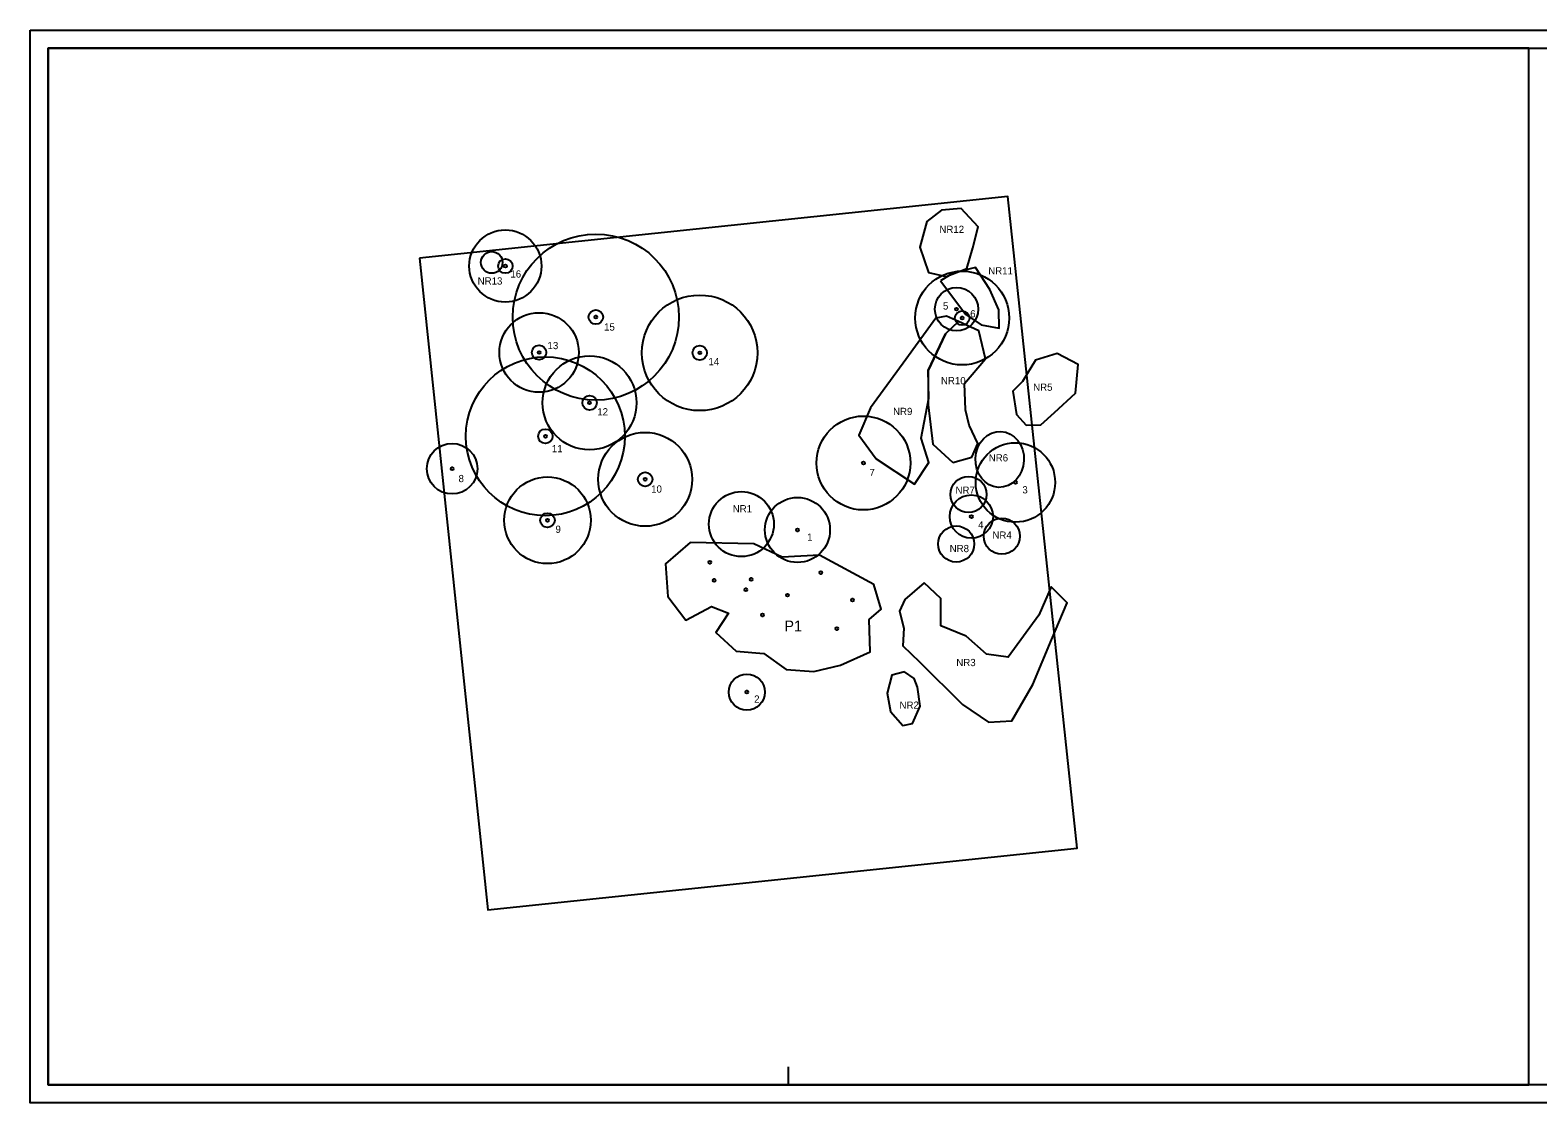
# Model space of a CAD drawing. Extents: x -539518 to -539203, y -1156262 to -1156114.
# Drawn here: x -539517.8 to -539309.1, y -1156262.1 to -1156113.6 of the extents above; entities that cross this region are included whole.
import ezdxf

# ---------------------------------------------------------------- set-up
doc = ezdxf.new("R2010")
doc.units = 0
for name, color, linetype in [('hranice řešeného území', 7, 'Continuous'), ('odstraňovaný keř', 7, 'Continuous'), ('odstraňovaný strom', 7, 'Continuous'), ('pěstební ošetření', 7, 'Continuous'), ('rámeček', 7, 'Continuous'), ('stávající keř', 7, 'Continuous'), ('stávající porost', 7, 'Continuous'), ('stávající strom', 7, 'Continuous'), ('text inventarizace', 7, 'Continuous')]:
    doc.layers.add(name, color=color, linetype=linetype)

msp = doc.modelspace()

# ---------------------------------------------------------------- linework, layer by layer
at = {"layer": 'hranice řešeného území'}
msp.add_lwpolyline([(-539463.88, -1156145.1), (-539454.44, -1156235.32), (-539372.85, -1156226.79), (-539382.42, -1156136.58)], close=True, dxfattribs=at)
at = {"layer": 'odstraňovaný keř'}
for centre, radius in [((-539453.9, -1156145.71), 1.5), ((-539387.89, -1156177.83), 2.5)]:
    msp.add_circle(centre, radius, dxfattribs=at)
msp.add_ellipse((-539383.56, -1156172.98), major_axis=(0.17, 3.87), ratio=0.867323, dxfattribs=at)
at = {"layer": 'odstraňovaný strom'}
for centre, radius in [((-539389.53, -1156152.19), 3), ((-539389.53, -1156152.19), 0.2), ((-539402.43, -1156173.48), 6.5), ((-539402.43, -1156173.48), 0.2), ((-539411.56, -1156182.75), 4.5), ((-539411.56, -1156182.75), 0.2)]:
    msp.add_circle(centre, radius, dxfattribs=at)
at = {"layer": 'pěstební ošetření'}
for centre in [(-539452.01, -1156146.21), (-539439.48, -1156153.28), (-539388.76, -1156153.41), (-539447.34, -1156158.18), (-539425.1, -1156158.23), (-539440.35, -1156165.15), (-539446.47, -1156169.78), (-539432.65, -1156175.74), (-539446.18, -1156181.41)]:
    msp.add_circle(centre, 1, dxfattribs=at)
at = {"layer": 'rámeček'}
msp.add_line((-539412.8, -1156259.56), (-539412.8, -1156257.06), dxfattribs=at)
for points in [[(-539517.8, -1156113.56), (-539202.8, -1156113.56), (-539202.8, -1156262.06), (-539517.8, -1156262.06)], [(-539310.3, -1156259.56), (-539310.3, -1156116.06), (-539515.3, -1156116.06), (-539515.3, -1156259.56)], [(-539515.3, -1156116.06), (-539205.3, -1156116.06), (-539205.3, -1156259.56), (-539515.3, -1156259.56)]]:
    msp.add_lwpolyline(points, close=True, dxfattribs=at)
at = {"layer": 'stávající keř'}
for points in [[(-539391.62, -1156138.48), (-539393.65, -1156140.04), (-539394.6, -1156143.62), (-539393.42, -1156147.13), (-539390.97, -1156147.65), (-539388.1, -1156146.54), (-539387.3, -1156143.71), (-539386.55, -1156140.78), (-539388.92, -1156138.25)], [(-539391.76, -1156148.27), (-539388.26, -1156152.91), (-539386.15, -1156154.37), (-539383.62, -1156154.82), (-539383.69, -1156152.26), (-539384.93, -1156149.45), (-539386.93, -1156146.43), (-539390.05, -1156147.2)], [(-539392.4, -1156153.42), (-539396.93, -1156159.64), (-539401.46, -1156165.86), (-539403.05, -1156169.61), (-539400.66, -1156172.91), (-539395.34, -1156176.41), (-539393.39, -1156173.43), (-539394.42, -1156170.02), (-539393.38, -1156164.51), (-539393.48, -1156160.66), (-539391.05, -1156155.62), (-539389.26, -1156153.91), (-539390.91, -1156153.15)], [(-539390.04, -1156173.4), (-539387.4, -1156172.65), (-539386.59, -1156170.8), (-539387.8, -1156168.26), (-539388.28, -1156166.1), (-539388.45, -1156162.48), (-539385.51, -1156159.07), (-539386.45, -1156155.18), (-539389.26, -1156153.91), (-539391.05, -1156155.62), (-539393.48, -1156160.66), (-539393.45, -1156165.42), (-539392.84, -1156170.86)], [(-539378.59, -1156159.24), (-539380.39, -1156162.21), (-539381.74, -1156163.53), (-539381.23, -1156166.77), (-539379.88, -1156168.23), (-539377.89, -1156168.19), (-539375.99, -1156166.47), (-539373.05, -1156163.81), (-539372.7, -1156159.86), (-539375.59, -1156158.32)], [(-539394.04, -1156190.09), (-539396.68, -1156192.36), (-539397.45, -1156193.98), (-539396.82, -1156196.34), (-539396.97, -1156198.79), (-539394.65, -1156201.01), (-539388.72, -1156206.92), (-539385.13, -1156209.36), (-539381.89, -1156209.19), (-539378.98, -1156204.15), (-539376.38, -1156197.94), (-539374.24, -1156192.83), (-539376.45, -1156190.63), (-539378.14, -1156194.56), (-539382.4, -1156200.37), (-539385.37, -1156199.96), (-539388.21, -1156197.46), (-539391.7, -1156196), (-539391.73, -1156192.22)], [(-539396.74, -1156202.39), (-539398.5, -1156202.84), (-539399.14, -1156205.34), (-539398.69, -1156207.88), (-539396.96, -1156209.8), (-539395.66, -1156209.53), (-539394.58, -1156207.13), (-539394.93, -1156204.52), (-539395.41, -1156203.32)]]:
    msp.add_lwpolyline(points, close=True, dxfattribs=at)
for centre, radius in [((-539419.33, -1156181.94), 4.5), ((-539389.58, -1156184.69), 2.5), ((-539383.26, -1156183.62), 2.5)]:
    msp.add_circle(centre, radius, dxfattribs=at)
at = {"layer": 'stávající porost'}
msp.add_lwpolyline([(-539426.42, -1156184.5), (-539429.82, -1156187.45), (-539429.53, -1156191.94), (-539427.03, -1156195.25), (-539423.45, -1156193.33), (-539421.11, -1156194.26), (-539422.86, -1156196.95), (-539420.03, -1156199.51), (-539416.23, -1156199.87), (-539413.11, -1156202.06), (-539409.31, -1156202.33), (-539405.6, -1156201.46), (-539401.48, -1156199.64), (-539401.65, -1156195.14), (-539399.99, -1156193.73), (-539400.97, -1156190.28), (-539408.51, -1156186.22), (-539413.68, -1156186.53), (-539417.6, -1156184.67)], close=True, dxfattribs=at)
at = {"layer": 'stávající strom'}
for centre, radius in [((-539452.01, -1156146.21), 5), ((-539439.48, -1156153.28), 11.5), ((-539452.01, -1156146.21), 0.2), ((-539388.76, -1156153.41), 6.5), ((-539425.1, -1156158.23), 8), ((-539447.34, -1156158.18), 5.5), ((-539439.48, -1156153.28), 0.2), ((-539388.76, -1156153.41), 0.2), ((-539446.47, -1156169.78), 11), ((-539447.34, -1156158.18), 0.2), ((-539440.35, -1156165.15), 6.5), ((-539425.1, -1156158.23), 0.2), ((-539440.35, -1156165.15), 0.2), ((-539446.47, -1156169.78), 0.2), ((-539432.65, -1156175.74), 6.5), ((-539459.38, -1156174.27), 3.5), ((-539381.39, -1156176.17), 5.5), ((-539459.38, -1156174.27), 0.2), ((-539446.18, -1156181.41), 6), ((-539432.65, -1156175.74), 0.2), ((-539381.39, -1156176.17), 0.2), ((-539387.49, -1156180.9), 3), ((-539446.18, -1156181.41), 0.2), ((-539387.49, -1156180.9), 0.2), ((-539423.7, -1156187.22), 0.2), ((-539408.31, -1156188.65), 0.2), ((-539423.08, -1156189.73), 0.2), ((-539418.71, -1156191.02), 0.2), ((-539417.98, -1156189.59), 0.2), ((-539412.93, -1156191.77), 0.2), ((-539403.95, -1156192.46), 0.2), ((-539416.41, -1156194.51), 0.2), ((-539406.12, -1156196.4), 0.2), ((-539418.58, -1156205.19), 2.5), ((-539418.58, -1156205.19), 0.2)]:
    msp.add_circle(centre, radius, dxfattribs=at)

# ---------------------------------------------------------------- texts
at = {"layer": 'text inventarizace'}
for s, p in [('NR12', (-539391.91, -1156141.63)), ('16', (-539451.31, -1156147.81)), ('NR11', (-539385.15, -1156147.37)), ('NR13', (-539455.84, -1156148.78)), ('5', (-539391.42, -1156152.24)), ('6', (-539387.65, -1156153.32)), ('15', (-539438.34, -1156155.15)), ('13', (-539446.17, -1156157.72)), ('14', (-539423.89, -1156159.94)), ('NR10', (-539391.7, -1156162.58)), ('NR5', (-539378.93, -1156163.48)), ('12', (-539439.28, -1156166.89)), ('NR9', (-539398.33, -1156166.84)), ('11', (-539445.57, -1156171.99)), ('NR6', (-539385.08, -1156173.26)), ('7', (-539401.6, -1156175.3)), ('8', (-539458.49, -1156176.13)), ('10', (-539431.82, -1156177.58)), ('NR7', (-539389.68, -1156177.74)), ('3', (-539380.42, -1156177.69)), ('NR1', (-539420.53, -1156180.31)), ('9', (-539445.07, -1156183.15)), ('4', (-539386.55, -1156182.54)), ('1', (-539410.23, -1156184.24)), ('NR8', (-539390.49, -1156185.82)), ('NR4', (-539384.57, -1156183.96)), ('NR3', (-539389.57, -1156201.6)), ('2', (-539417.56, -1156206.66)), ('NR2', (-539397.43, -1156207.5))]:
    msp.add_text(s, height=1, dxfattribs=at).set_placement(p)
msp.add_text('P1', height=1.5, rotation=360, dxfattribs=at).set_placement((-539413.38, -1156196.79))

doc.saveas('drawing.dxf')
